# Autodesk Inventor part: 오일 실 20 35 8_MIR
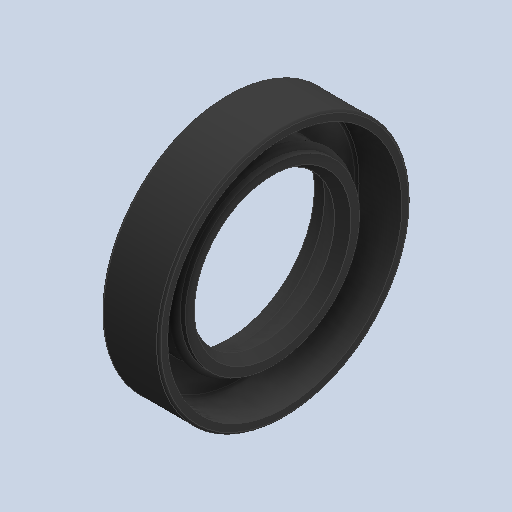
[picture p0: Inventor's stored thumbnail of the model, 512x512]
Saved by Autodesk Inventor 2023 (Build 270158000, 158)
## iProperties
Created: 2026-06
Part Number: 오일 실 20 35 8_MIR
Material: 고무
Description: 오일-실
Document SubType Name: Modeling
Designer: home
Density: 0.93 g/cm^3
Appearance: 기본값
Author: jhkim
Sending System: Autodesk Inventor 2027
Preprocessor: ST-DEVELOPER v20.1
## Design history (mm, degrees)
derived "오일 실 20 35 8.ipt"
feature "솔리드1::오일 실 20 35 8.ipt" dims "d0" = 10
tag "피쳐 태그1"
node "솔리드1"
